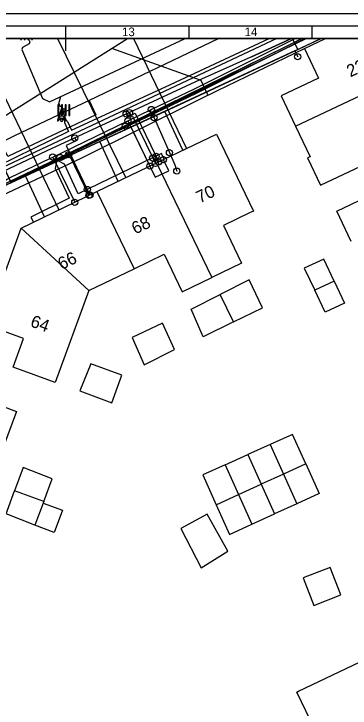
# Model space of a CAD drawing. Extents: x 192672 to 192910, y 446344 to 446512.
# Drawn here: x 192786.4 to 192813.8, y 446455.3 to 446511.8 of the extents above; entities that cross this region are included whole.
import ezdxf

# ---------------------------------------------------------------- set-up
doc = ezdxf.new("R2010")
doc.units = 0
for name, color, linetype in [('1010 viewport', 7, 'Continuous'), ('B-OI-KL-BUISLEIDING_OLIEGASCHEMICALIEN_GASLAGEDRUK-G', 7, 'Continuous'), ('B-OI-KL-DATA-G', 7, 'Continuous'), ('B-OI-KL-DATA_GTWP-S', 7, 'Continuous'), ('B-OI-KL-DATA_HULPSTUK-S', 7, 'Continuous'), ('B-OI-KL-DATA_KABELBED-G', 7, 'Continuous'), ('B-OI-KL-DATA_MOF-S', 7, 'Continuous'), ('B-OI-KL-DATA_OVERIG-S', 7, 'Continuous'), ('B-OI-KL-ET_LS-G', 7, 'Continuous'), ('B-OI-KL-ET_LS_DELIVERYPOINT-S', 7, 'Continuous'), ('B-OI-KL-ET_LS_MOF-S', 7, 'Continuous'), ('B-OI-KL-GAS_LD_AFTAKZADEL-S', 7, 'Continuous'), ('B-OI-KL-GAS_LD_DELIVERYPOINT-S', 7, 'Continuous'), ('B-OI-KL-GAS_LD_MANTELBUIS-G', 7, 'Continuous'), ('B-OI-KL-GAS_LD_OVERGANGSSTUK-S', 7, 'Continuous'), ('B-OI-KL-WATER-G', 7, 'Continuous'), ('B-OI-RI-RIOOLVRIJVERVAL-G', 7, 'Continuous'), ('bovenleidingmast', 7, 'Continuous'), ('Default', 7, 'Continuous'), ('huisnummerreeks BGT', 7, 'Continuous'), ('kant open verharding', 7, 'Continuous'), ('kolk', 7, 'Continuous'), ('Luifel', 7, 'Continuous'), ('pand op maaiveld vlak', 7, 'Continuous'), ('verkeerseiland - berm', 7, 'Continuous'), ('X-XX-AL-TEKENBLAD-S', 7, 'Continuous')]:
    doc.layers.add(name, color=color, linetype=linetype)

# ---------------------------------------------------------------- blocks, each defined once
blk = doc.blocks.new('B-OI-KL-DATA_HULPSTUK-S')
at = {"layer": 'Default'}
blk.add_circle((0, 0), 0.25, dxfattribs=at)
blk = doc.blocks.new('B-OI-KL-GAS_LD_AFTAKZADEL-S')
at = {"layer": 'Default'}
blk.add_circle((0, 0), 0.25, dxfattribs=at)
blk = doc.blocks.new('B-OI-KL-GAS_LD_DELIVERYPOINT-S')
at = {"layer": 'Default'}
blk.add_circle((0, 0), 0.25, dxfattribs=at)
blk = doc.blocks.new('B-OI-KL-GAS_LD_OVERGANGSSTUK-S')
at = {"layer": 'Default'}
blk.add_circle((0, 0), 0.25, dxfattribs=at)
blk = doc.blocks.new('B-OI-KL-ET_LS_DELIVERYPOINT-S')
at = {"layer": 'Default'}
blk.add_circle((0, 0), 0.25, dxfattribs=at)
blk = doc.blocks.new('B-OI-KL-ET_LS_MOF-S')
at = {"layer": 'Default'}
blk.add_circle((0, 0), 0.25, dxfattribs=at)
blk = doc.blocks.new('B-OI-KL-DATA_OVERIG-S')
at = {"layer": 'Default'}
blk.add_circle((0, 0), 0.25, dxfattribs=at)
blk = doc.blocks.new('B-OI-KL-DATA_GTWP-S')
at = {"layer": 'Default'}
blk.add_circle((0, 0), 0.25, dxfattribs=at)
blk = doc.blocks.new('B-OI-KL-DATA_MOF-S')
at = {"layer": 'Default'}
blk.add_circle((0, 0), 0.25, dxfattribs=at)

msp = doc.modelspace()

# ---------------------------------------------------------------- linework, layer by layer
at = {"layer": '1010 viewport'}
msp.add_lwpolyline([(192675.743, 446509.756), (192860.643, 446509.756), (192860.643, 446345.556), (192675.743, 446345.556)], close=True, dxfattribs=at)
at = {"layer": 'B-OI-KL-BUISLEIDING_OLIEGASCHEMICALIEN_GASLAGEDRUK-G'}
for points in [[(192808.99, 446509.756), (192805.748, 446508.276), (192801.187, 446506.24), (192794.261, 446502.995), (192789.059, 446500.595), (192784.967, 446498.672), (192784.158, 446498.207), (192778.689, 446484.216), (192775.51, 446475.031), (192756.472, 446424.494), (192754.598, 446419.974), (192751.089, 446410.462)], [(192795.563, 446503.605), (192795.669, 446503.379), (192795.841, 446503.459), (192795.888, 446503.36), (192796.081, 446503.45), (192797.72, 446500.044)], [(192795.835, 446503.732), (192795.941, 446503.506), (192796.305, 446503.677), (192797.991, 446500.174)], [(192791.391, 446501.671), (192791.495, 446501.443), (192790.68, 446501.067), (192792.404, 446497.486)], [(192797.991, 446500.174), (192798.208, 446499.724)], [(192797.72, 446500.044), (192797.937, 446499.594)], [(192792.404, 446497.486), (192792.621, 446497.035)]]:
    msp.add_lwpolyline(points, dxfattribs=at)
at = {"layer": 'B-OI-KL-DATA-G'}
for points in [[(192745.236, 446436.264), (192745.276, 446436.371), (192749.491, 446434.791), (192749.794, 446435.599), (192768.74, 446486.807), (192770.369, 446486.306), (192778.924, 446483.081), (192784.343, 446497.176), (192794.941, 446502.078), (192811.396, 446509.756)], [(192757.844, 446425.655), (192756.715, 446426.08), (192759.12, 446432.478), (192750.822, 446435.215), (192749.794, 446435.599), (192768.74, 446486.807), (192770.369, 446486.306), (192778.924, 446483.081), (192784.343, 446497.176), (192794.941, 446502.078), (192811.396, 446509.756)], [(192757.844, 446425.655), (192756.715, 446426.08), (192759.12, 446432.478), (192750.822, 446435.215), (192749.794, 446435.599), (192768.74, 446486.807), (192770.369, 446486.306), (192778.924, 446483.081), (192784.343, 446497.176), (192794.941, 446502.078), (192811.396, 446509.756)], [(192757.844, 446425.655), (192756.715, 446426.08), (192759.12, 446432.478), (192750.822, 446435.215), (192749.794, 446435.599), (192768.74, 446486.807), (192770.369, 446486.306), (192778.924, 446483.081), (192784.343, 446497.176), (192794.941, 446502.078), (192811.396, 446509.756)], [(192757.844, 446425.655), (192756.715, 446426.08), (192759.12, 446432.478), (192750.822, 446435.215), (192749.794, 446435.599), (192768.74, 446486.807), (192770.369, 446486.306), (192778.924, 446483.081), (192784.343, 446497.176), (192794.941, 446502.078), (192811.396, 446509.756)], [(192757.844, 446425.655), (192756.715, 446426.08), (192759.12, 446432.478), (192750.822, 446435.215), (192749.794, 446435.599), (192768.74, 446486.807), (192770.369, 446486.306), (192778.924, 446483.081), (192784.343, 446497.176), (192794.941, 446502.078), (192811.396, 446509.756)], [(192757.844, 446425.655), (192756.715, 446426.08), (192759.12, 446432.478), (192750.822, 446435.215), (192749.794, 446435.599), (192768.74, 446486.807), (192770.369, 446486.306), (192778.924, 446483.081), (192784.343, 446497.176), (192794.941, 446502.078), (192811.396, 446509.756)], [(192757.844, 446425.655), (192756.715, 446426.08), (192759.12, 446432.478), (192750.822, 446435.215), (192749.794, 446435.599), (192768.74, 446486.807), (192770.369, 446486.306), (192778.924, 446483.081), (192784.343, 446497.176), (192794.941, 446502.078), (192811.396, 446509.756)], [(192764.304, 446509.756), (192770.565, 446496.734), (192770.867, 446495.7), (192770.986, 446494.71), (192770.973, 446493.522), (192770.841, 446492.782), (192768.74, 446486.807), (192770.369, 446486.306), (192778.924, 446483.081), (192784.343, 446497.176), (192794.941, 446502.078), (192809.504, 446508.873), (192809.089, 446509.756)], [(192764.304, 446509.756), (192770.565, 446496.734), (192770.867, 446495.7), (192770.986, 446494.71), (192770.973, 446493.522), (192770.841, 446492.782), (192768.74, 446486.807), (192770.369, 446486.306), (192778.924, 446483.081), (192784.343, 446497.176), (192794.941, 446502.078), (192809.504, 446508.873), (192809.089, 446509.756)], [(192768.74, 446486.807), (192770.369, 446486.306), (192778.924, 446483.081), (192784.343, 446497.176), (192794.941, 446502.078), (192811.396, 446509.756)], [(192809.87, 446509.756), (192801.3, 446505.5), (192786.2, 446498.1), (192785, 446500.6), (192781.5, 446507.8), (192779.7, 446509.5), (192779.582, 446509.756)], [(192809.883, 446509.756), (192786.2, 446498.1), (192781.5, 446507.8), (192779.7, 446509.5), (192779.582, 446509.756)], [(192809.883, 446509.756), (192786.2, 446498.1), (192781.5, 446507.8), (192779.7, 446509.5), (192779.582, 446509.756)], [(192779.601, 446509.756), (192779.727, 446509.493), (192781.507, 446507.825), (192784.974, 446500.615), (192786.203, 446498.061), (192789.931, 446499.854), (192801.292, 446505.317), (192810.12, 446509.756)], [(192779.601, 446509.756), (192779.727, 446509.493), (192781.507, 446507.825), (192784.974, 446500.615), (192786.203, 446498.061), (192789.931, 446499.854), (192801.292, 446505.317), (192810.12, 446509.756)], [(192779.727, 446509.493), (192781.507, 446507.825), (192784.974, 446500.615), (192786.203, 446498.061), (192789.931, 446499.854), (192801.292, 446505.317), (192810.12, 446509.756)], [(192809.501, 446508.269), (192809.266, 446508.761), (192809.504, 446508.873), (192809.089, 446509.756)], [(192809.501, 446508.269), (192809.266, 446508.761), (192809.504, 446508.873), (192809.089, 446509.756)], [(192809.501, 446508.269), (192809.266, 446508.761), (192809.504, 446508.873), (192809.089, 446509.756)], [(192809.501, 446508.269), (192809.266, 446508.761), (192809.504, 446508.873), (192809.089, 446509.756)], [(192809.501, 446508.269), (192809.266, 446508.761), (192809.504, 446508.873), (192809.089, 446509.756)], [(192809.501, 446508.269), (192809.266, 446508.761), (192809.504, 446508.873), (192809.089, 446509.756)], [(192809.501, 446508.269), (192809.266, 446508.761), (192809.504, 446508.873), (192809.089, 446509.756)], [(192809.501, 446508.269), (192809.266, 446508.761), (192809.504, 446508.873), (192809.089, 446509.756)], [(192809.501, 446508.269), (192809.266, 446508.761), (192811.397, 446509.756)], [(192809.501, 446508.269), (192809.266, 446508.761), (192811.397, 446509.756)], [(192809.501, 446508.269), (192809.266, 446508.761), (192811.397, 446509.756)], [(192809.501, 446508.269), (192809.266, 446508.761), (192811.397, 446509.756)], [(192809.501, 446508.269), (192809.266, 446508.761), (192811.397, 446509.756)], [(192809.501, 446508.269), (192809.266, 446508.761), (192811.397, 446509.756)], [(192809.501, 446508.269), (192809.266, 446508.761), (192811.397, 446509.756)], [(192809.501, 446508.269), (192809.266, 446508.761), (192811.397, 446509.756)], [(192809.501, 446508.269), (192809.266, 446508.761), (192811.397, 446509.756)], [(192809.501, 446508.269), (192809.266, 446508.761), (192811.397, 446509.756)], [(192768.74, 446486.807), (192770.369, 446486.306), (192778.924, 446483.081), (192784.343, 446497.176), (192794.941, 446502.078), (192809.266, 446508.761), (192809.501, 446508.269)], [(192809.501, 446508.269), (192809.266, 446508.761), (192794.941, 446502.078), (192784.343, 446497.176), (192778.924, 446483.081), (192778.438, 446481.788), (192779.283, 446481.47)], [(192784.723, 446488.03), (192781.328, 446489.335), (192784.343, 446497.176), (192794.941, 446502.078), (192809.266, 446508.761), (192809.501, 446508.269)], [(192788.92, 446495.253), (192787.381, 446498.581), (192794.941, 446502.078), (192809.266, 446508.761), (192809.501, 446508.269)], [(192794.925, 446498.144), (192793.429, 446501.379), (192794.941, 446502.078), (192809.266, 446508.761), (192809.501, 446508.269)], [(192800.176, 446500.671), (192798.702, 446503.832), (192809.266, 446508.761), (192809.501, 446508.269)], [(192798.656, 446499.94), (192798.435, 446500.397), (192791.675, 446497.132), (192790.54, 446499.551), (192789.931, 446499.854)], [(192789.931, 446499.854), (192789.796, 446499.188), (192790.931, 446496.77), (192787.828, 446495.227), (192788.023, 446494.823)]]:
    msp.add_lwpolyline(points, dxfattribs=at)
at = {"layer": 'B-OI-KL-DATA_KABELBED-G'}
for q in [(192809.089, 446509.756), (192811.391, 446509.756)]:
    msp.add_line((192809.504, 446508.873), q, dxfattribs=at)
for points in [[(192785.331, 446497.94), (192785.605, 446498.139), (192785.892, 446498.318), (192786.191, 446498.476), (192789.352, 446500), (192789.594, 446500.117), (192795.704, 446503.063), (192797.607, 446503.981), (192801.113, 446505.672), (192809.291, 446509.756)], [(192798.702, 446503.832), (192809.266, 446508.761)], [(192809.266, 446508.761), (192809.504, 446508.873)], [(192809.266, 446508.761), (192809.501, 446508.269)], [(192793.429, 446501.379), (192798.702, 446503.832)], [(192797.613, 446503.988), (192797.607, 446503.981), (192797.521, 446503.883), (192797.827, 446503.314)], [(192800.176, 446500.671), (192798.702, 446503.832)], [(192795.704, 446503.063), (192797.499, 446499.383)], [(192797.827, 446503.314), (192799.081, 446500.477)], [(192787.381, 446498.581), (192793.429, 446501.379)], [(192794.925, 446498.144), (192793.429, 446501.379)], [(192789.594, 446500.117), (192789.594, 446500.117), (192791.387, 446496.441)], [(192799.081, 446500.477), (192799.519, 446499.483), (192799.68, 446498.977)], [(192781.328, 446489.335), (192784.343, 446497.176), (192787.381, 446498.581)], [(192788.92, 446495.253), (192787.381, 446498.581)]]:
    msp.add_lwpolyline(points, dxfattribs=at)
at = {"layer": 'B-OI-KL-ET_LS-G'}
for points in [[(192807.795, 446509.756), (192785.465, 446499.231), (192784.279, 446497.948), (192782.198, 446492.212), (192772.784, 446495.238), (192772.082, 446495.48), (192769.274, 446501.433)], [(192810.223, 446509.756), (192801.246, 446505.403), (192785.389, 446497.771), (192774.175, 446493.36)], [(192790.564, 446503.228), (192790.806, 446502.995), (192791.12, 446502.308), (192798.755, 446505.834), (192807.182, 446509.756)], [(192790.564, 446503.228), (192790.567, 446502.921), (192790.865, 446502.188), (192785.098, 446499.379), (192784.052, 446498.05), (192776.999, 446479.133), (192776.611, 446479.298), (192776.274, 446479.242)], [(192795.491, 446502.633), (192795.599, 446502.407), (192795.955, 446502.579), (192797.495, 446499.381)], [(192790.19, 446500.082), (192790.298, 446499.856), (192790.997, 446500.192), (192792.536, 446496.994)], [(192797.495, 446499.381), (192797.929, 446498.48), (192799.019, 446499.004), (192798.585, 446499.905)]]:
    msp.add_lwpolyline(points, dxfattribs=at)
at = {"layer": 'B-OI-KL-GAS_LD_MANTELBUIS-G'}
msp.add_line((192805.748, 446508.276), (192808.99, 446509.756), dxfattribs=at)
at = {"layer": 'B-OI-KL-WATER-G'}
for p, q in [((192783.407, 446509.756), (192790.1, 446495.821)), ((192789.973, 446509.756), (192795.531, 446498.435)), ((192796.168, 446509.756), (192800.472, 446500.814))]:
    msp.add_line(p, q, dxfattribs=at)
at = {"layer": 'B-OI-RI-RIOOLVRIJVERVAL-G'}
msp.add_line((192779.05, 446499.28), (192795.666, 446509.756), dxfattribs=at)
for points in [[(192787.601, 446509.756), (192787.728, 446509.478), (192787.677, 446509.309), (192787.138, 446509.02), (192787.087, 446508.851), (192788.778, 446504.886), (192789.334, 446504.603), (192800.363, 446509.756)], [(192794.369, 446508.979), (192801.626, 446506.381), (192802.17, 446505.215)], [(192790.246, 446504.169), (192790.1, 446504.481), (192790.267, 446505.036)]]:
    msp.add_lwpolyline(points, dxfattribs=at)
at = {"layer": 'bovenleidingmast'}
for p, q in [((192790.32, 446504.087), (192789.979, 446503.114)), ((192790.679, 446503.114), (192790.338, 446504.087))]:
    msp.add_line(p, q, dxfattribs=at)
msp.add_lwpolyline([(192790.451, 446503.464), (192790.521, 446503.264), (192790.137, 446503.264), (192790.207, 446503.464)], close=True, dxfattribs=at)
for points in [[(192790.338, 446503.784), (192790.416, 446503.564), (192790.242, 446503.564), (192790.32, 446503.784)], [(192790.073, 446503.081), (192790.102, 446503.164), (192790.242, 446503.164)], [(192790.416, 446503.164), (192790.556, 446503.164), (192790.585, 446503.081)]]:
    msp.add_lwpolyline(points, dxfattribs=at)
for centre, radius, start, end in [((192790.329, 446504.084), 0.01, 19.29, 160.71), ((192790.329, 446503.781), 0.01, 19.29, 160.71), ((192790.026, 446503.097), 0.05, 160.71, 340.71), ((192790.329, 446503.114), 0.1, 0, 180), ((192790.329, 446503.114), 0.1, 180, 0), ((192790.329, 446503.114), 0.1, 30, 150), ((192790.632, 446503.097), 0.05, 199.29, 19.29)]:
    msp.add_arc(centre, radius, start, end, dxfattribs=at)
at = {"layer": 'kant open verharding'}
msp.add_line((192803.101, 446509.756), (192792.545, 446504.728), dxfattribs=at)
msp.add_lwpolyline([(192779.53, 446482.124), (192780.051, 446483.746), (192784.415, 446495.597), (192785.528, 446497.018), (192791.864, 446500), (192801.451, 446504.762), (192802.996, 446505.531), (192810.052, 446508.944)], dxfattribs=at)
at = {"layer": 'kolk'}
for points in [[(192787.071, 446509.756), (192786.986, 446509.756), (192786.986, 446509.684), (192787.071, 446509.684)], [(192787.369, 446509.756), (192787.284, 446509.756), (192787.284, 446509.684), (192787.369, 446509.684)], [(192787.666, 446509.756), (192787.581, 446509.756), (192787.581, 446509.684), (192787.666, 446509.684)], [(192787.964, 446509.756), (192787.879, 446509.756), (192787.879, 446509.684), (192787.964, 446509.684)], [(192790.101, 446503.927), (192790.101, 446504.352), (192790.016, 446504.352), (192790.016, 446503.927), (192790.016, 446503.502), (192790.101, 446503.502)], [(192790.399, 446503.927), (192790.399, 446504.352), (192790.314, 446504.352), (192790.314, 446503.927), (192790.314, 446503.502), (192790.399, 446503.502)], [(192790.696, 446503.927), (192790.696, 446504.352), (192790.611, 446504.352), (192790.611, 446503.927), (192790.611, 446503.502), (192790.696, 446503.502)], [(192790.994, 446503.927), (192790.994, 446504.352), (192790.909, 446504.352), (192790.909, 446503.927), (192790.909, 446503.502), (192790.994, 446503.502)]]:
    msp.add_lwpolyline(points, close=True, dxfattribs=at)
for start, end in [(0, 180), (180, 0)]:
    msp.add_arc((192790.505, 446503.927), 0.1, start, end, dxfattribs=at)
at = {"layer": 'Luifel'}
for points in [[(192812.464, 446490.035), (192813.315, 446488.246), (192811.741, 446487.497), (192810.89, 446489.286)], [(192788.813, 446471.993), (192790.383, 446471.415), (192789.719, 446469.611), (192788.149, 446470.189)]]:
    msp.add_lwpolyline(points, dxfattribs=at)
at = {"layer": 'pand op maaiveld vlak'}
for p, q in [((192810.052, 446508.944), (192811.759, 446509.756)), ((192809.329, 446502.618), (192818.666, 446507.065)), ((192793.189, 446497.308), (192798.04, 446499.643)), ((192798.04, 446499.643), (192802.523, 446490.331)), ((192787.037, 446494.347), (192793.189, 446497.308)), ((192793.189, 446497.308), (192796.205, 446491.041)), ((192792.525, 446489.271), (192787.037, 446494.347)), ((192792.525, 446489.271), (192796.205, 446491.041)), ((192812.464, 446490.035), (192810.89, 446489.286)), ((192804.284, 446486.712), (192803.202, 446488.946)), ((192807.259, 446476.75), (192805.437, 446475.926)), ((192807.259, 446476.75), (192808.343, 446474.342)), ((192803.614, 446475.101), (192805.437, 446475.926)), ((192805.437, 446475.926), (192806.523, 446473.515)), ((192803.614, 446475.101), (192804.701, 446472.687)), ((192810.165, 446475.169), (192808.343, 446474.342)), ((192808.343, 446474.342), (192806.523, 446473.515)), ((192808.343, 446474.342), (192809.428, 446471.933)), ((192788.861, 446472.123), (192786.504, 446472.992)), ((192804.701, 446472.687), (192806.523, 446473.515)), ((192806.523, 446473.515), (192807.608, 446471.104)), ((192802.88, 446471.86), (192804.701, 446472.687)), ((192804.701, 446472.687), (192805.787, 446470.274)), ((192788.813, 446471.993), (192788.149, 446470.189)), ((192788.861, 446472.123), (192788.813, 446471.993)), ((192809.428, 446471.933), (192807.608, 446471.104)), ((192805.787, 446470.274), (192807.608, 446471.104))]:
    msp.add_line(p, q, dxfattribs=at)
for points in [[(192810.052, 446508.944), (192811.2, 446506.531), (192808.156, 446505.081), (192809.329, 446502.618)], [(192809.329, 446502.618), (192810.506, 446500.147), (192810.302, 446500.05), (192811.352, 446497.825), (192814.631, 446499.387)], [(192798.04, 446499.643), (192802.893, 446501.979), (192805.903, 446495.725), (192805.591, 446495.575), (192803.461, 446494.549), (192804.933, 446491.491), (192802.523, 446490.331)], [(192813.859, 446493.264), (192812.693, 446495.713), (192815.699, 446497.145), (192814.631, 446499.387)], [(192792.525, 446489.271), (192789.784, 446481.79), (192786.371, 446483.041), (192787.224, 446485.369), (192784.159, 446486.492), (192787.037, 446494.347)], [(192796.205, 446491.041), (192798.647, 446492.217), (192800.113, 446489.171), (192802.523, 446490.331)], [(192812.464, 446490.035), (192811.612, 446491.824), (192810.038, 446491.074), (192810.89, 446489.286)], [(192804.284, 446486.712), (192806.652, 446487.86), (192805.57, 446490.129), (192803.202, 446488.946)], [(192804.284, 446486.712), (192801.813, 446485.514), (192800.833, 446487.762), (192803.202, 446488.946)], [(192799.494, 446484.467), (192798.505, 446486.618), (192796.055, 446485.455), (192797.016, 446483.224), (192799.494, 446484.467)], [(192795.209, 446482.388), (192792.694, 446483.304), (192791.799, 446481.108), (192794.407, 446480.126), (192795.209, 446482.388)], [(192779.53, 446482.124), (192786.658, 446479.438), (192784.508, 446473.734)], [(192810.165, 446475.169), (192809.081, 446477.575), (192807.259, 446476.75)], [(192788.861, 446472.123), (192789.539, 446473.962), (192787.186, 446474.872), (192786.504, 446472.992)], [(192803.614, 446475.101), (192801.792, 446474.276), (192802.88, 446471.86)], [(192810.165, 446475.169), (192811.248, 446472.763), (192809.428, 446471.933)], [(192788.149, 446470.189), (192785.822, 446471.111), (192786.504, 446472.992)], [(192802.88, 446471.86), (192803.967, 446469.444), (192805.787, 446470.274)], [(192803.82, 446468.077), (192802.143, 446471.084), (192800.001, 446469.917), (192801.666, 446466.73), (192803.82, 446468.077)], [(192810.813, 446463.676), (192813.005, 446464.519), (192812.149, 446466.745), (192809.957, 446465.901), (192810.813, 446463.676)], [(192811.054, 446451.801), (192810.545, 446453.32), (192810.916, 446453.523), (192809.437, 446456.628), (192809.575, 446456.694), (192822.797, 446462.99)]]:
    msp.add_lwpolyline(points, dxfattribs=at)
at = {"layer": 'verkeerseiland - berm'}
for points in [[(192792.545, 446504.728), (192793.101, 446503.55), (192785.941, 446500.151), (192785.412, 446501.292)], [(192792.545, 446504.728), (192786.498, 446501.848), (192785.412, 446501.292)]]:
    msp.add_lwpolyline(points, dxfattribs=at)
at = {"layer": 'X-XX-AL-TEKENBLAD-S'}
for p, q in [((192909.543, 446511.756), (192671.743, 446511.756)), ((192908.543, 446510.756), (192674.743, 446510.756)), ((192800.643, 446510.756), (192800.643, 446509.756)), ((192810.643, 446510.756), (192810.643, 446509.756))]:
    msp.add_line(p, q, dxfattribs=at)
msp.add_lwpolyline([(192790.643, 446510.756), (192790.643, 446508.756)], dxfattribs=at)
msp.add_lwpolyline([(192675.743, 446345.556), (192907.543, 446345.556), (192907.543, 446509.756), (192675.743, 446509.756)], close=True, dxfattribs=at)

# ---------------------------------------------------------------- block references
at = {"layer": 'B-OI-KL-DATA_GTWP-S'}
for p in [(192797.613, 446503.988), (192797.827, 446503.314), (192797.827, 446503.314), (192795.704, 446503.063), (192799.081, 446500.477), (192799.081, 446500.477), (192789.594, 446500.117), (192797.499, 446499.383), (192799.68, 446498.977), (192791.387, 446496.441)]:
    msp.add_blockref('B-OI-KL-DATA_GTWP-S', p, dxfattribs=at)
at = {"layer": 'B-OI-KL-DATA_HULPSTUK-S'}
msp.add_blockref('B-OI-KL-DATA_HULPSTUK-S', (192809.501, 446508.269), dxfattribs=at)
at = {"layer": 'B-OI-KL-DATA_MOF-S'}
for p in [(192797.613, 446503.988), (192797.827, 446503.314), (192795.704, 446503.063), (192799.081, 446500.477), (192789.594, 446500.117)]:
    msp.add_blockref('B-OI-KL-DATA_MOF-S', p, dxfattribs=at)
at = {"layer": 'B-OI-KL-DATA_OVERIG-S'}
msp.add_blockref('B-OI-KL-DATA_OVERIG-S', (192790.9, 446500.3), dxfattribs=at)
at = {"layer": 'B-OI-KL-ET_LS_DELIVERYPOINT-S'}
for p in [(192798.585, 446499.905), (192797.495, 446499.381), (192792.536, 446496.994)]:
    msp.add_blockref('B-OI-KL-ET_LS_DELIVERYPOINT-S', p, dxfattribs=at)
at = {"layer": 'B-OI-KL-ET_LS_MOF-S'}
for p in [(192795.491, 446502.633), (192790.19, 446500.082)]:
    msp.add_blockref('B-OI-KL-ET_LS_MOF-S', p, dxfattribs=at)
at = {"layer": 'B-OI-KL-GAS_LD_AFTAKZADEL-S'}
for p in [(192795.563, 446503.605), (192795.835, 446503.732), (192791.391, 446501.671)]:
    msp.add_blockref('B-OI-KL-GAS_LD_AFTAKZADEL-S', p, dxfattribs=at)
at = {"layer": 'B-OI-KL-GAS_LD_DELIVERYPOINT-S'}
for p in [(192797.937, 446499.594), (192798.208, 446499.724), (192792.621, 446497.035)]:
    msp.add_blockref('B-OI-KL-GAS_LD_DELIVERYPOINT-S', p, dxfattribs=at)
at = {"layer": 'B-OI-KL-GAS_LD_OVERGANGSSTUK-S'}
for p in [(192797.72, 446500.044), (192797.991, 446500.174), (192792.404, 446497.486)]:
    msp.add_blockref('B-OI-KL-GAS_LD_OVERGANGSSTUK-S', p, dxfattribs=at)

# ---------------------------------------------------------------- texts
at = {"layer": 'huisnummerreeks BGT'}
for s, rotation, p in [('23', 25.5, (192813.772, 446506.583)), ('70', 25.7, (192801.548, 446496.337)), ('68', 25.7, (192796.306, 446493.815)), ('66', 25.7, (192790.317, 446490.931)), ('64', 339.9, (192787.709, 446486.374))]:
    msp.add_text(s, height=1, rotation=rotation, dxfattribs=at).set_placement(p)
at = {"layer": 'X-XX-AL-TEKENBLAD-S'}
for s, p in [('13', (192795.223, 446509.945)), ('14', (192805.189, 446509.945))]:
    msp.add_text(s, height=0.7, dxfattribs=at).set_placement(p)

doc.saveas('drawing.dxf')
